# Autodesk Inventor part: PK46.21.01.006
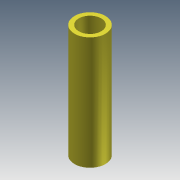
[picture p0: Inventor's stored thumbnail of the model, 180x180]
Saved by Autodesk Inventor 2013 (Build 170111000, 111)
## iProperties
Created: 2005-04
Part Number: PK46.21.01.006
Material: Steel, Mild
Document SubType Name: Modeling
Designer: salex
Manufacturer: Standard
Standards Organization: Custom
Density: 7.86 g/cm^3
Author: salex
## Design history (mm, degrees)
sketch "Эскиз1"
  geometry: C1 r 79.5 at (0, 0); C2 r 109.5 at (0, 0)
  constraints: 2 centre point, 1 coincident, 1 other
  dimensions: "d0" = 219 diameter of C2; "d1" = 159 diameter of C1
extrude "Выдавливание1" new body sketch "Эскиз1" distance "d2" = 800; taper "d3" = 0 deg
body "Solid1"
